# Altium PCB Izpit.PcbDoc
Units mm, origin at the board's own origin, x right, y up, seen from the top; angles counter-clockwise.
Board outline 115 x 60 mm, 2 copper layers (Top Layer, Bottom Layer); 7 components, 19 nets, 84 pads, 0 vias.
Unrouted connection lines stored in the file: 29.
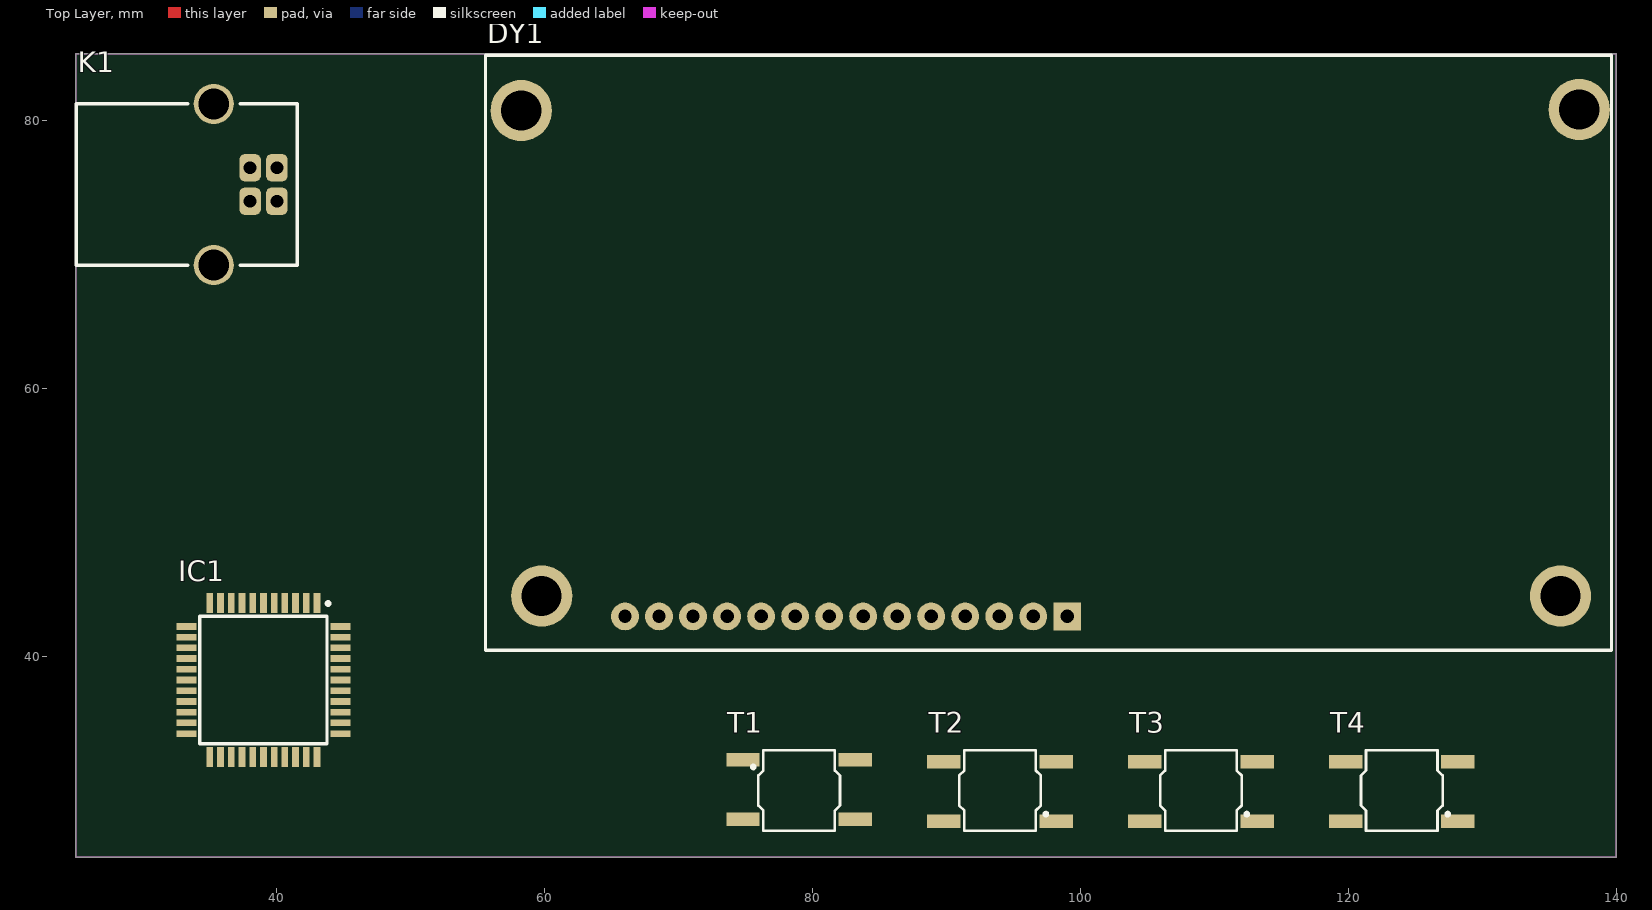
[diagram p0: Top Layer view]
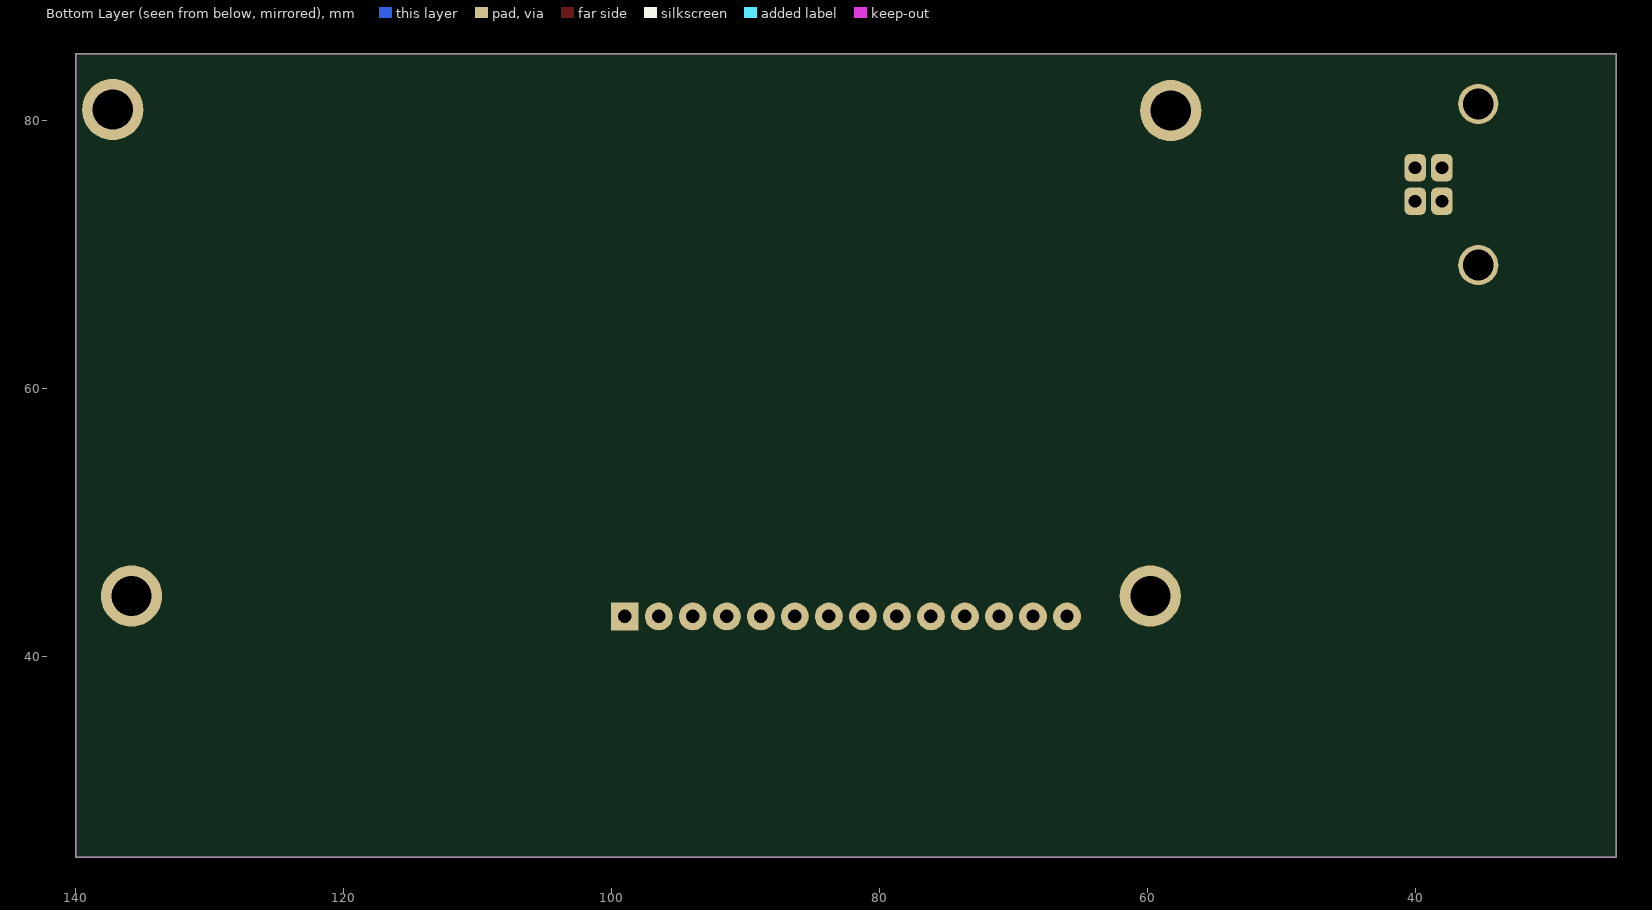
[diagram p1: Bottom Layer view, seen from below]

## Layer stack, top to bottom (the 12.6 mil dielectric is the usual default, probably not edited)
Top Layer: signal copper 0.0356
Dielectric: dielectric 0.32, FR-4, Dk 4.8
Bottom Layer: signal copper 0.0356

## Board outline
25,25 25,85 140,85 140,25

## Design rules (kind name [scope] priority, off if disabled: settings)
Clearance [All] p1: gap=0.254
PolygonConnect [All] p1: connectstyle=Relief reliefconductorwidth=0.254 reliefentries=4 polygonreliefangle="90 Angle"
RoutingVias [All] p1: holewidth=0.711 width=1.27 viastyle="Through Hole" minholewidth=0.711 minwidth=1.27 maxholewidth=0.711 maxwidth=1.27
SilkscreenOverComponentPads [All] p1: minsilkscreentomaskgap=0.254
SolderMaskExpansion [All] p1: expansion=0.102
Width [All] p1: maxlimit=0.254 minlimit=0.254 preferedwidth=0.254
27 further rules are at their usual default settings.

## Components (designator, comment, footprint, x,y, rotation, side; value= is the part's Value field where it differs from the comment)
DY1 "LCD_HC16201" _LCD_LCD_HC16201(Primary) 66,43 r90 top
IC1 "ATMEGA324PA" TQFP44 43,44 r270 top
K1 "USB-B" _USB_B_90_F_USB-B-90F(Primary) 38,74 r90 top
T1 "MINI 6X6" "SW 5x6 SMD SHORT" 79,30 r0 top
T2 "MINI 6X6" "SW 5x6 SMD SHORT" 94,30 r180 top
T3 "MINI 6X6" "SW 5x6 SMD SHORT" 109,30 r180 top
T4 "MINI 6X6" "SW 5x6 SMD SHORT" 124,30 r180 top

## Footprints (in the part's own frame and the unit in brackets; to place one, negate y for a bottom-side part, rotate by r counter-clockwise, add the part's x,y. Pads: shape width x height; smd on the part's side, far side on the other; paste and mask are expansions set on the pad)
_LCD_LCD_HC16201(Primary) [mil]
  round 180 hole 118: 15(1487,305) 16(1490,-2805) 17(60,-2750) 18(60,245)
  round 82 hole 39.37: Contrast(0,-1100) DB0(0,-700) DB1(0,-600) DB2(0,-500) DB3(0,-400) DB4(0,-300) DB5(0,-200) DB6(0,-100) DB7(0,0) E(0,-800) R/W(0,-900) RS(0,-1000) VDD(0,-1200)
  rect 82x82 hole 39.37: VSS(0,-1300)
  silkscreen extent -100,-2900 1650,410
_USB_B_90_F_USB-B-90F(Primary) [mm]
  rrect50% 2.032x1.6 hole 0.965: 1(0,-2.005) 2(2.5,-2.005) 3(2.5,-0.005) 4(0,-0.005)
  round 3 hole 2.3: 5(-4.77,2.705) 6(7.27,2.705)
  silkscreen extent -4.77,-3.51 7.27,12.99
"SW 5x6 SMD SHORT" [mm]
  rect 2.5x1 smd: 1(-4.191,2.286) 2(-4.191,-2.159) 3(4.191,-2.159) 4(4.191,2.286)
  silkscreen extent -3.55,-3 3.05,3, body extent -4.44,-2.92 4.56,3.08, height 5
TQFP44 [mm]
  rect 1.5x0.5 smd: 1(0,0) 2(0,-0.8) 3(0,-1.6) 4(0,-2.4) 5(0,-3.2) 6(0,-4) 7(0,-4.801) 8(0,-5.601) 9(0,-6.401) 10(0,-7.201) 11(0,-8.001) 23(11.5,-8.001) 24(11.5,-7.201) 25(11.5,-6.401) 26(11.5,-5.601) 27(11.5,-4.801) 28(11.5,-4) 29(11.5,-3.2) 30(11.5,-2.4) 31(11.5,-1.6) 32(11.5,-0.8) 33(11.5,0)
  rect 0.5x1.5 smd: 12(1.749,-9.75) 13(2.549,-9.75) 14(3.35,-9.75) 15(4.15,-9.75) 16(4.95,-9.75) 17(5.75,-9.75) 18(6.55,-9.75) 19(7.35,-9.75) 20(8.15,-9.75) 21(8.95,-9.75) 22(9.75,-9.75) 34(9.75,1.749) 35(8.95,1.749) 36(8.15,1.749) 37(7.35,1.749) 38(6.55,1.749) 39(5.75,1.749) 40(4.95,1.749) 41(4.15,1.749) 42(3.35,1.749) 43(2.549,1.749) 44(1.749,1.749)
  silkscreen extent -0.09,-8.75 10.5,0.95, body extent -0.25,-9.99 11.75,2.01, height 1.02

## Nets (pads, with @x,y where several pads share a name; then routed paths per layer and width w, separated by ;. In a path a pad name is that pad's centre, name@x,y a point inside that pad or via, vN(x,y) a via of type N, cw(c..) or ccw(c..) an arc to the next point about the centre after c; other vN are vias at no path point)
D4: DY1.DB4 IC1.40
D5: DY1.DB5 IC1.41
D6: DY1.DB6 IC1.42
D7: DY1.DB7 IC1.43
E: DY1.E IC1.1
GND: DY1.DB0 DY1.DB1 DY1.DB2 DY1.DB3 DY1.VSS IC1.6 IC1.18 IC1.28 IC1.39 K1.4 T1.1 T2.1 T3.1 T4.1
NetC6_1: IC1.7
NetC7_1: IC1.8
NetD1_1: K1.3
NetD2_1: K1.2
NetIC1_11: IC1.11
NetIC1_12: IC1.12
NetIC1_34: IC1.34 T4.2
NetIC1_35: IC1.35 T3.2
NetIC1_36: IC1.36 T2.2
NetIC1_37: IC1.37 T1.2
RS: DY1.RS IC1.3
RW: DY1.R/W IC1.2
VCC: DY1.VDD IC1.5 IC1.17 IC1.27 IC1.38 K1.1
pads on no net: DY1.15 DY1.16 DY1.17 DY1.18 DY1.Contrast IC1.4 IC1.9 IC1.10 IC1.13 IC1.14 IC1.15 IC1.16 IC1.19 IC1.20 IC1.21 IC1.22 IC1.23 IC1.24 IC1.25 IC1.26 IC1.29 IC1.30 IC1.31 IC1.32 IC1.33 IC1.44 K1.5 K1.6 T1.3 T1.4 T2.3 T2.4 T3.3 T3.4 T4.3 T4.4

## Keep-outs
Keep-Out Layer:
  lines w0.102: 25,25 140,25 140,85 41,85 25,85 25,25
